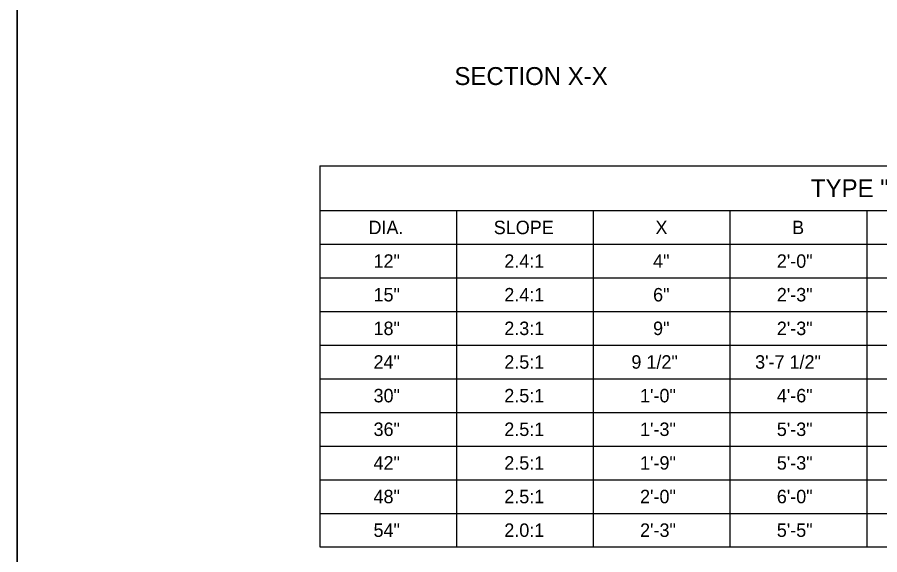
# Model space of a CAD drawing. Extents: x 49991.4 to 50021, y 49987.6 to 50011.4.
# Drawn here: x 49999.383 to 50003.231, y 49992.942 to 49995.339 of the extents above; entities that cross this region are included whole.
import ezdxf

# ---------------------------------------------------------------- set-up
doc = ezdxf.new("R2010")
doc.units = 0
doc.layers.add('Level 1', color=7, linetype='Continuous')
doc.layers.add('Level 2', color=7, linetype='Continuous')

msp = doc.modelspace()

# ---------------------------------------------------------------- linework, layer by layer
at = {"layer": 'Level 1'}
msp.add_lwpolyline([(49999.3835, 49998.9992), (50016.7501, 49998.9992), (50016.7501, 49987.7988), (49999.3835, 49987.7988)], close=True, dxfattribs=at)
at = {"layer": 'Level 2'}
for p, q in [((49999.3835, 49998.9992), (49999.3835, 49987.7988)), ((50000.7327, 49994.677), (50000.7327, 49992.977)), ((50000.7327, 49994.677), (50005.6127, 49994.677)), ((50000.7327, 49994.477), (50005.6127, 49994.477)), ((50001.3427, 49994.477), (50001.3427, 49992.977)), ((50001.9527, 49994.477), (50001.9527, 49992.977)), ((50002.5627, 49994.477), (50002.5627, 49992.977)), ((50003.1727, 49994.477), (50003.1727, 49992.977)), ((50000.7327, 49994.327), (50005.6127, 49994.327)), ((50000.7327, 49994.177), (50005.6127, 49994.177)), ((50000.7327, 49994.027), (50005.6127, 49994.027)), ((50000.7327, 49993.877), (50005.6127, 49993.877)), ((50000.7327, 49993.727), (50005.6127, 49993.727)), ((50000.7327, 49993.577), (50005.6127, 49993.577)), ((50000.7327, 49993.427), (50005.6127, 49993.427)), ((50000.7327, 49993.277), (50005.6127, 49993.277)), ((50000.7327, 49993.127), (50005.6127, 49993.127)), ((50000.7327, 49992.977), (50005.6127, 49992.977))]:
    msp.add_line(p, q, dxfattribs=at)

# ---------------------------------------------------------------- texts
for s, height, p in [('SECTION X-X', 0.08, (50001.3337, 49995.037)), ('TYPE "A"', 0.08, (50002.9239, 49994.537)), ('DIA.', 0.06, (50000.9502, 49994.372)), ('SLOPE', 0.06, (50001.5089, 49994.372)), ('X', 0.06, (50002.2303, 49994.372)), ('B', 0.06, (50002.84, 49994.372)), ('12"', 0.06, (50000.9728, 49994.222)), ('2.4:1', 0.06, (50001.556, 49994.222)), ('4"', 0.06, (50002.2197, 49994.222)), ('2\'-0"', 0.06, (50002.7716, 49994.222)), ('15"', 0.06, (50000.9728, 49994.072)), ('2.4:1', 0.06, (50001.556, 49994.072)), ('6"', 0.06, (50002.2197, 49994.072)), ('2\'-3"', 0.06, (50002.7716, 49994.072)), ('18"', 0.06, (50000.9728, 49993.922)), ('2.3:1', 0.06, (50001.556, 49993.922)), ('9"', 0.06, (50002.2197, 49993.922)), ('2\'-3"', 0.06, (50002.7716, 49993.922)), ('24"', 0.06, (50000.9728, 49993.772)), ('2.5:1', 0.06, (50001.556, 49993.772)), ('9 1/2"', 0.06, (50002.123, 49993.772)), ('3\'-7 1/2"', 0.06, (50002.6749, 49993.772)), ('30"', 0.06, (50000.9728, 49993.622)), ('2.5:1', 0.06, (50001.556, 49993.622)), ('1\'-0"', 0.06, (50002.1616, 49993.622)), ('4\'-6"', 0.06, (50002.7716, 49993.622)), ('36"', 0.06, (50000.9728, 49993.472)), ('2.5:1', 0.06, (50001.556, 49993.472)), ('1\'-3"', 0.06, (50002.1616, 49993.472)), ('5\'-3"', 0.06, (50002.7716, 49993.472)), ('42"', 0.06, (50000.9728, 49993.322)), ('2.5:1', 0.06, (50001.556, 49993.322)), ('1\'-9"', 0.06, (50002.1616, 49993.322)), ('5\'-3"', 0.06, (50002.7716, 49993.322)), ('48"', 0.06, (50000.9728, 49993.172)), ('2.5:1', 0.06, (50001.556, 49993.172)), ('2\'-0"', 0.06, (50002.1616, 49993.172)), ('6\'-0"', 0.06, (50002.7716, 49993.172)), ('54"', 0.06, (50000.9728, 49993.022)), ('2.0:1', 0.06, (50001.556, 49993.022)), ('2\'-3"', 0.06, (50002.1616, 49993.022)), ('5\'-5"', 0.06, (50002.7716, 49993.022))]:
    msp.add_text(s, height=height, dxfattribs=at).set_placement(p)

doc.saveas('drawing.dxf')
